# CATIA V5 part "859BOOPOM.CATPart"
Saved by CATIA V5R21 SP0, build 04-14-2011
Part number: 859BOOPOM
Source: Unknown
Bounding box of the stored display mesh (mm): x -20 to 20, y -14 to 24, z -59.2 to 32.299
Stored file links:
  C:\Users\ALI OZGUN\Desktop\alhan\859BOOPOM.CATPart
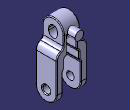
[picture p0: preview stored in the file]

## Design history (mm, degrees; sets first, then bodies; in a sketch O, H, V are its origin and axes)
Body1 "859-KASATSIMA" (main body)
  Solid1: solid without history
